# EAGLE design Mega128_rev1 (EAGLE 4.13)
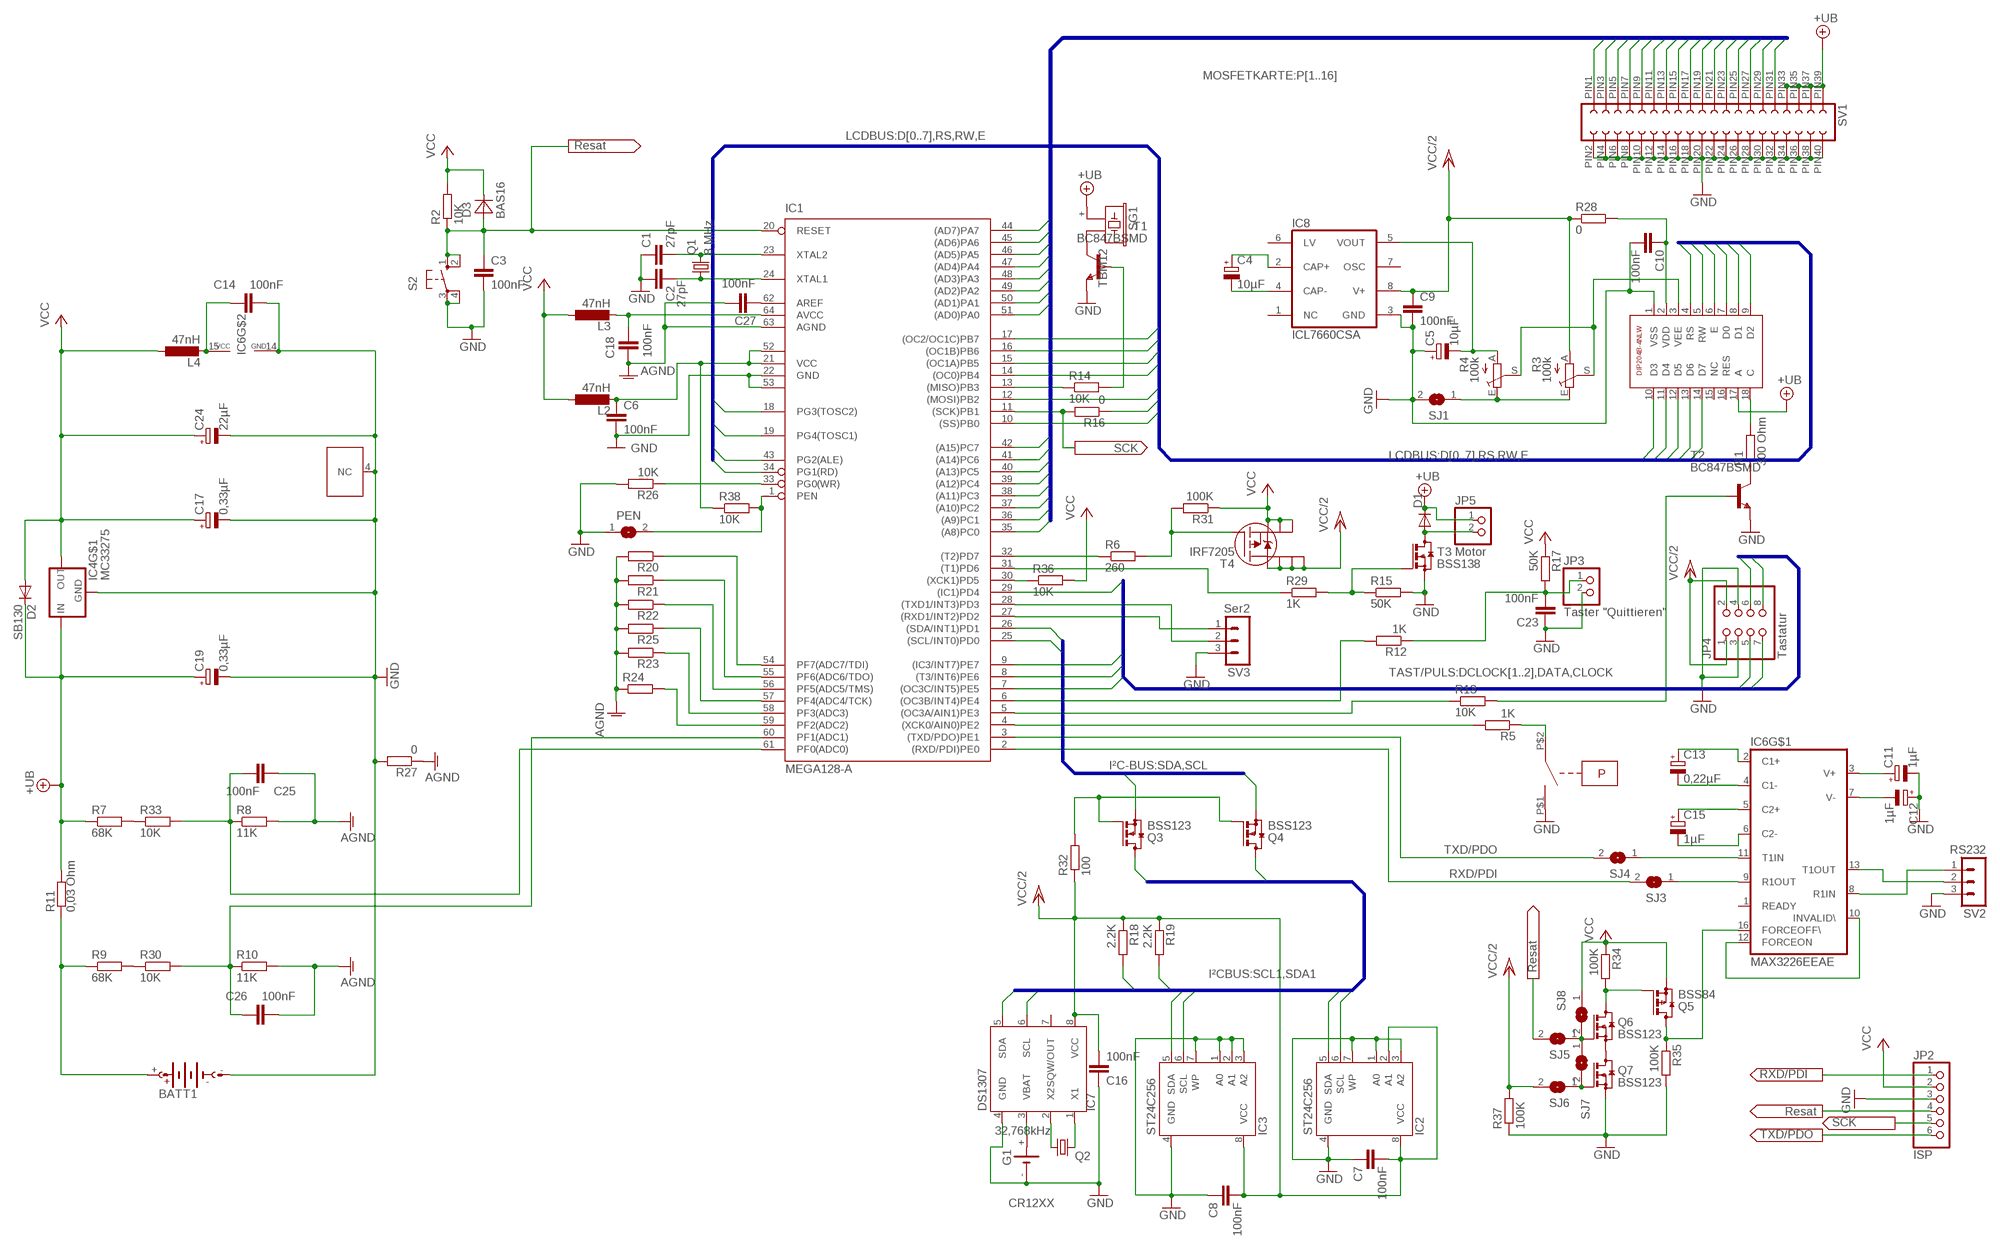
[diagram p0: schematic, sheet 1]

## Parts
BATT1  LITHIUM11.1  [AB9V]
C1  27pF  C-EUC0805K  [C0805K]
C2  27pF  C-EUC0805K  [C0805K]
C3  100nF  C-EUC0805K  [C0805K]
C4  10µF  CPOL-EUC/6032-28R  [C/6032-28R]
C5  10µF  CPOL-EUC/6032-28R  [C/6032-28R]
C6  100nF  C-EUC0805K  [C0805K]
C7  100nF  C-EUC0805K  [C0805K]
C8  100nF  C-EUC0805K  [C0805K]
C9  100nF  C-EUC0805K  [C0805K]
C10  100nF  C-EUC0805K  [C0805K]
C11  1µF  CPOL-EUA  [PANASONIC_A]
C12  1µF  CPOL-EUA  [PANASONIC_A]
C13  0,22µF  CPOL-EUA  [PANASONIC_A]
C14  100nF  C-EUC0805K  [C0805K]
C15  1µF  CPOL-EUA  [PANASONIC_A]
C16  100nF  C-EUC0805K  [C0805K]
C17  0,33µF  CPOL-EUA/3216-18R  [A/3216-18R]
C18  100nF  C-EUC0805K  [C0805K]
C19  0,33µF  CPOL-EUA/3216-18R  [A/3216-18R]
C23  100nF  C-EUC0805K  [C0805K]
C24  22µF  CPOL-EU085CS-1AR  [085CS_1AR]
C25  100nF  C-EUC0805K  [C0805K]
C26  100nF  C-EUC0805K  [C0805K]
C27  100nF  C-EUC0805K  [C0805K]
D1  DIODE-MICROMELF-W  [MICROMELF-W]
D2  SB130  DIODE-F126-10  [F126-10]
D3  BAS16  [SOT23]
G1  CR12XX  [CR12XXH]
IC1  MEGA128-A  [TQFP64]
IC2  ST24C256  AT24C  [SOIC8]
IC3  ST24C256  AT24C  [SOIC8]
IC4  MC33275  [SOT223]
IC6  MAX3226EEAE  [SSOP16]
IC7  DS1307  [SOIC-8]
IC8  ICL7660CSA  [SO08]
JP2  ISP  PINHD-1X6  [1X06]
JP3  Taster "Quittieren"  PINHD-1X2  [1X02]
JP4  Tastatur  PINHD-2X4  [2X04]
JP5  Motor  PINHD-1X2  [1X02]
L2  47nH  L-EU0805  [R0805]
L3  47nH  L-EU0805  [R0805]
L4  47nH  L-EU0805  [R0805]
PEN  SJ  [SJ]
Q1  8 MHz  CRYTALHC49U-V  [HC49U-V]
Q2  32,768kHz  CRYTALTC26H  [TC26H]
Q3  BSS123  [SOT23]
Q4  BSS123  [SOT23]
Q5  BSS84  [SOT23]
Q6  BSS123  [SOT23]
Q7  BSS123  [SOT23]
R1  300 Ohm  R-EU_M1206  [M1206]
R2  10K  R-EU_R0805W  [R0805W]
R3  100k  TRIM_EU-S75H  [S75H]
R4  100k  TRIM_EU-S75H  [S75H]
R5  1K  R-EU_R0805W  [R0805W]
R6  260  R-EU_R0805W  [R0805W]
R7  68K  R-EU_R0805W  [R0805W]
R8  11K  R-EU_R0805W  [R0805W]
R9  68K  R-EU_R0805W  [R0805W]
R10  11K  R-EU_R0805W  [R0805W]
R11  0,03 Ohm  13F  [13F]
R12  1K  R-EU_R0805W  [R0805W]
R13  10K  R-EU_R0805W  [R0805W]
R14  10K  R-EU_R0805W  [R0805W]
R15  50K  R-EU_R0805W  [R0805W]
R16  0  R-EU_R0805W  [R0805W]
R17  50K  R-EU_R0805W  [R0805W]
R18  2.2K  R-EU_R0805W  [R0805W]
R19  2.2K  R-EU_R0805W  [R0805W]
R20  R-EU_R0805W  [R0805W]
R21  R-EU_R0805W  [R0805W]
R22  R-EU_R0805W  [R0805W]
R23  R-EU_R0805W  [R0805W]
R24  R-EU_R0805W  [R0805W]
R25  R-EU_R0805W  [R0805W]
R26  10K  R-EU_R0805W  [R0805W]
R27  0  R-EU_R0805W  [R0805W]
R28  0  R-EU_R0805W  [R0805W]
R29  1K  R-EU_R0805W  [R0805W]
R30  10K  R-EU_R0805W  [R0805W]
R31  100K  R-EU_R0805W  [R0805W]
R32  100  R-EU_R0805W  [R0805W]
R33  10K  R-EU_R0805W  [R0805W]
R34  100K  R-EU_R0805W  [R0805W]
R35  100K  R-EU_R0805W  [R0805W]
R36  10K  R-EU_R0805W  [R0805W]
R37  100K  R-EU_R0805W  [R0805W]
R38  10K  R-EU_R0805W  [R0805W]
S1  Druckschalter  6761  [6761]
S2  10-XX  [B3F-10XX]
SG1  TBM12  TBM05  [F/CM12P]
SJ1  SJ  [SJ]
SJ3  SJ  [SJ]
SJ4  SJ  [SJ]
SJ5  SJ  [SJ]
SJ6  SJ  [SJ]
SJ7  SJ  [SJ]
SJ8  SJ  [SJ]
SV1  FE20-2W2MMRAST  [FE20-2W-2MM]
SV2  RS232  MA03-1  [MA03-1]
SV3  Ser2  MA03-1  [MA03-1]
T1  BC847BSMD  [SOT23]
T2  BC847BSMD  [SOT23]
T3  BSS138  [SOT23]
T4  IRF7205  [SO8-2]
U$2  DIP204B-4NLW  [DIP204B-4NLW]

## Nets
+UB [pwr]: C19.+ D1.C D2.C IC4.1(IN) JP5.1 R7.1 R11.P$1 SG1.+ SV1.PIN33 SV1.PIN35 SV1.PIN37 SV1.PIN39 U$2.17(A)
AGND: C18.1 C25.2 C26.1 C27.2 IC1.63(AGND) R8.2 R10.2 R20.2 R21.2 R22.2 R23.2 R24.1 R25.2 R27.1
B+: BATT1.+ R9.1 R11.P$2
CLOCK: IC1.7((OC3C/INT5)PE5) JP4.8
D0: IC1.34(PG1(RD)) U$2.7(D0)
D1: IC1.43(PG2(ALE)) U$2.8(D1)
D2: IC1.19(PG4(TOSC1)) U$2.9(D2)
D3: IC1.18(PG3(TOSC2)) U$2.10(D3)
D4: IC1.14((OC0)PB4) U$2.11(D4)
D5: IC1.15((OC1A)PB5) U$2.12(D5)
D6: IC1.16((OC1B)PB6) U$2.13(D6)
D7: IC1.17((OC2/OC1C)PB7) U$2.14(D7)
DATA: IC1.29((IC1)PD4) JP4.6
DCLOCK1: IC1.9((IC3/INT7)PE7) JP4.5
DCLOCK2: IC1.8((T3/INT6)PE6) JP4.7
E: IC1.12((MOSI)PB2) U$2.6(E)
GND: BATT1.- C1.1 C2.2 C3.2 C5.+ C6.2 C7.1 C8.1 C9.2 C10.2 C11.- C12.+ C14.1 C16.1 C17.- C19.- C23.1 C24.- G1.- IC1.22(GND) IC1.53(GND1) IC2.1(A0) IC2.3(A2) IC2.4(GND) IC2.7(WP) IC3.1(A0) IC3.2(A1) IC3.3(A2) IC3.4(GND) IC3.7(WP) IC4.2(GND) IC4.4(NC) IC6.14(GND) IC7.4(GND) IC8.3(GND) JP2.3 JP3.2 JP4.3 JP4.4 PEN.1 Q7.2(S) R15.2 R26.2 R27.2 R35.2 R37.1 S1.P$1 S2.3(P) S2.4(P1) SJ1.2 SV1.PIN2 SV1.PIN4 SV1.PIN6 SV1.PIN8 SV1.PIN10 SV1.PIN12 SV1.PIN14 SV1.PIN16 SV1.PIN18 SV1.PIN20 SV1.PIN22 SV1.PIN24 SV1.PIN26 SV1.PIN28 SV1.PIN30 SV1.PIN32 SV1.PIN34 SV1.PIN36 SV1.PIN38 SV1.PIN40 SV2.3 SV3.3 T1.2(E) T2.2(E) T3.2(S) U$2.1(VSS)
IBATT: C25.1 IC1.61(PF0(ADC0)) R8.1 R33.2
N$1: IC7.2(X2) Q2.1
N$2: IC7.1(X1) Q2.2
N$3: C4.+ IC8.2(CAP+)
N$4: C5.- IC8.5(VOUT) R4.A
N$5: C4.- IC8.4(CAP-)
N$6 [pwr]: R1.2 U$2.18(C)
N$7: R3.S R4.S U$2.3(VEE)
N$8: IC1.4((XCK0/AIN0)PE2) R5.2
N$9: C27.1 IC1.62(AREF)
N$10: IC6.13(T1OUT) SV2.2
N$11: R13.2 T2.1(B)
N$12: R5.1 S1.P$2
N$13: R3.E R4.E SJ1.1
N$14: IC1.5((OC3A/AIN1)PE3) R13.1
N$15: IC1.13((MISO)PB3) R14.1
N$16: C10.1 R28.2 U$2.2(VDD)
N$17: C11.+ IC6.3(V+)
N$18: C12.- IC6.7(V-)
N$19: Q3.1(G) Q4.1(G) R32.2
N$20: IC1.54(PF7(ADC7/TDI)) R20.1
N$21: R9.2 R30.1
N$22: C15.- IC6.6(C2-)
N$23: C15.+ IC6.5(C2+)
N$24: C13.- IC6.4(C1-)
N$25: C13.+ IC6.2(C1+)
N$26: IC6.8(R1IN) SV2.1
N$27: IC1.32((T2)PD7) R6.1
N$28: IC1.6((OC3B/INT4)PE4) R12.2
N$29: C23.2 JP3.1 R12.1 R17.2
N$30: R1.1 T2.3(C)
N$31: IC1.55(PF6(ADC6/TDO)) R21.1
N$32: IC1.1(PEN) PEN.2 R38.2
N$33: C1.2 IC1.23(XTAL2) Q1.2
N$34: C2.1 IC1.24(XTAL1) Q1.1
N$35: R15.1 R29.2 T3.1(G)
N$36: SG1.- T1.3(C)
N$37: R14.2 T1.1(B)
N$38: R6.2 R31.2 T4.4(G)
N$39: G1.+ IC7.3(VBAT)
N$40: IC1.33(PG0(WR)) R26.1
N$41: C6.1 IC1.21(VCC) IC1.52(VCC1) L2.2 R38.1
N$42: IC1.56(PF5(ADC5/TMS)) R22.1
N$43: C18.2 IC1.64(AVCC) L3.2
N$44: IC1.58(PF3(ADC3)) R23.1
N$45 [pwr]: D1.A JP5.2 T3.3(D)
N$46: IC1.59(PF2(ADC2)) R24.2
N$48: IC6.11(T1IN) SJ4.1
N$49: IC6.9(R1OUT) SJ3.1
N$50: R7.2 R33.1
N$51: IC1.31((T1)PD6) R29.1
N$52: C14.2 IC6.15(VCC) L4.2
N$53: IC1.28((TXD1/INT3)PD3) SV3.2
N$54: IC1.27((RXD1/INT2)PD2) SV3.1
N$55: Q6.2(S) Q7.3(D)
N$56: Q5.1(G) Q6.3(D) R34.2
N$57: Q6.1(G) SJ5.1 SJ7.1 SJ8.2
N$58: IC6.16(FORCEOFF\) Q5.3(D) R35.1
N$59: Q7.1(G) SJ6.1 SJ7.2
N$60: IC1.30((XCK1)PD5) R36.1
N$61: IC1.57(PF4(ADC4/TCK)) R25.1
P1: IC1.51((AD0)PA0) SV1.PIN31
P2: IC1.50((AD1)PA1) SV1.PIN29
P3: IC1.49((AD2)PA2) SV1.PIN27
P4: IC1.48((AD3)PA3) SV1.PIN25
P5: IC1.47((AD4)PA4) SV1.PIN23
P6: IC1.46((AD5)PA5) SV1.PIN21
P7: IC1.45((AD6)PA6) SV1.PIN19
P8: IC1.44((AD7)PA7) SV1.PIN17
P9: IC1.35((A8)PC0) SV1.PIN1
P10: IC1.36((A9)PC1) SV1.PIN3
P11: IC1.37((A10)PC2) SV1.PIN5
P12: IC1.38((A11)PC3) SV1.PIN7
P13: IC1.39((A12)PC4) SV1.PIN9
P14: IC1.40((A13)PC5) SV1.PIN11
P15: IC1.41((A14)PC6) SV1.PIN13
P16: IC1.42((A15)PC7) SV1.PIN15
RESAT: C3.1 D3.1(A) IC1.20(RESET) JP2.4 R2.1 S2.1(S) S2.2(S1) SJ5.2
RS: IC1.10((SS)PB0) U$2.4(RS)
RW: R16.1 U$2.5(RW)
RXD/PDI: IC1.2((RXD/PDI)PE0) IC6.10(INVALID\) IC6.12(FORCEON) JP2.1 SJ3.2
SCK: IC1.11((SCK)PB1) JP2.5 R16.2
SCL: IC1.25((SCL/INT0)PD0) Q4.2(S) R19.2
SCL1 [pwr]: IC2.6(SCL) IC3.6(SCL) IC7.6(SCL) Q4.3(D)
SDA: IC1.26((SDA/INT1)PD1) Q3.2(S) R18.2
SDA1 [pwr]: IC2.5(SDA) IC3.5(SDA) IC7.5(SDA) Q3.3(D)
TXD/PDO: IC1.3((TXD/PDO)PE1) JP2.6 SJ4.2
VBATT: C26.2 IC1.60(PF1(ADC1)) R10.1 R30.2
VCC: C17.+ C24.+ D2.A D3.3(C) IC4.3(OUT) JP2.2 L2.1 L3.1 L4.1 Q5.2(S) R2.2 R17.1 R31.1 R34.1 R36.2 SJ8.1 T4.1(S) T4.2(S1) T4.3(S2)
VCC/2: C7.2 C8.2 C9.1 C16.2 IC2.2(A1) IC2.8(VCC) IC3.8(VCC) IC7.8(VCC) IC8.8(V+) JP4.1 JP4.2 R3.A R18.1 R19.1 R28.1 R32.1 R37.2 SJ6.2 T4.5(D) T4.6(D) T4.7(D) T4.8(D)
Unconnected: IC6.1(READY) IC7.7(SQW/OUT) IC8.1(NC) IC8.6(LV) IC8.7(OSC) U$2.15(NC) U$2.16(RES)

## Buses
MOSFETKARTE:P[1..16]
LCDBUS:D[0..7],RS,RW,E
TAST/PULS:DCLOCK[1..2],DATA,CLOCK
I²CBUS:SCL1,SDA1
I²C-BUS:SDA,SCL

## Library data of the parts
BATT1 = battery:LITHIUM11.1
C1-C3 C6-C10 C14 C16 C18 C23 C25-C27 = rcl:C-EU: CAPACITOR, European symbol
C4 C5 C11-C13 C15 C17 C19 C24 = rcl:CPOL-EU: POLARIZED CAPACITOR, European symbol
D1 D2 = diode:DIODE-: DIODE
D3 = diode:BAS16: BAS16
G1 = battery:CR12XX
IC1 = avr:MEGA128: MICROCONTROLLER 128 Kbytes FLASH 4 Kbytes SRAM 4 Kbytes EEPROM DUAL USART 8-channel 10 bit ADC
IC2 IC3 = atmel:AT24C*: 2-wire serial EEPROM
IC4 = v-reg:MC33275: LDO Spannungsregler von ON Semiconductor * niedriger Stromverbrauch im Leerlauf * Vin max: 13V * Vout: 5V * Iout: 300mA
IC6 = maxim:MAX3226EEAE
IC7 = dallas:DS1307: I2C Serial RTC w/56 bytes battery backed RAM
IC8 = maxim:ICL7660CSA: VOLTAGE CONVERTER
JP2 = pinhead:PINHD-1X6: PIN HEADER
JP3 JP5 = pinhead:PINHD-1X2: PIN HEADER
JP4 = pinhead:PINHD-2X4: PIN HEADER
L2-L4 = rcl:L-EU: INDUCTOR, European symbol
PEN SJ1 SJ3-SJ8 = jumper:SJ: SMD solder JUMPER
Q1 Q2 = crystal:CRYTAL: CRYSTAL
Q3 Q4 Q6 Q7 = transistor-small-signal:BSS123: N-CHANNEL MOS FET
Q5 = transistor-small-signal:BSS84: P-CHANNEL MOS FET
R1 R2 R5-R10 R12-R38 = rcl:R-EU_: RESISTOR, European symbol
R3 R4 = pot:TRIM_EU-: POTENTIOMETER
R11 = resistor-shunt:13F
S1 = herga:6761
S2 = switch-omron:10-XX: OMRON SWITCH
SG1 = buzzer:TBM05: BUZZER
SV1 = con-lsta:FE20-2W: FEMALE HEADER
SV2 SV3 = con-lstb:MA03-1: PIN HEADER
T1 T2 = transistor-npn:BC847*: NPN Transistor
T3 = transistor-small-signal:BSS138
T4 = irf-2:IRF7205: IRF7205 P-Channel Hexfet von International Rectifier VDSS = -30V RDS(on) = 0.070 Ohm @ -10V ID = -4.6A
U$2 = dip204b-4nlw:DIP204B-4NLW

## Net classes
1 pwr: width 0.61 mm, clearance 0.61 mm

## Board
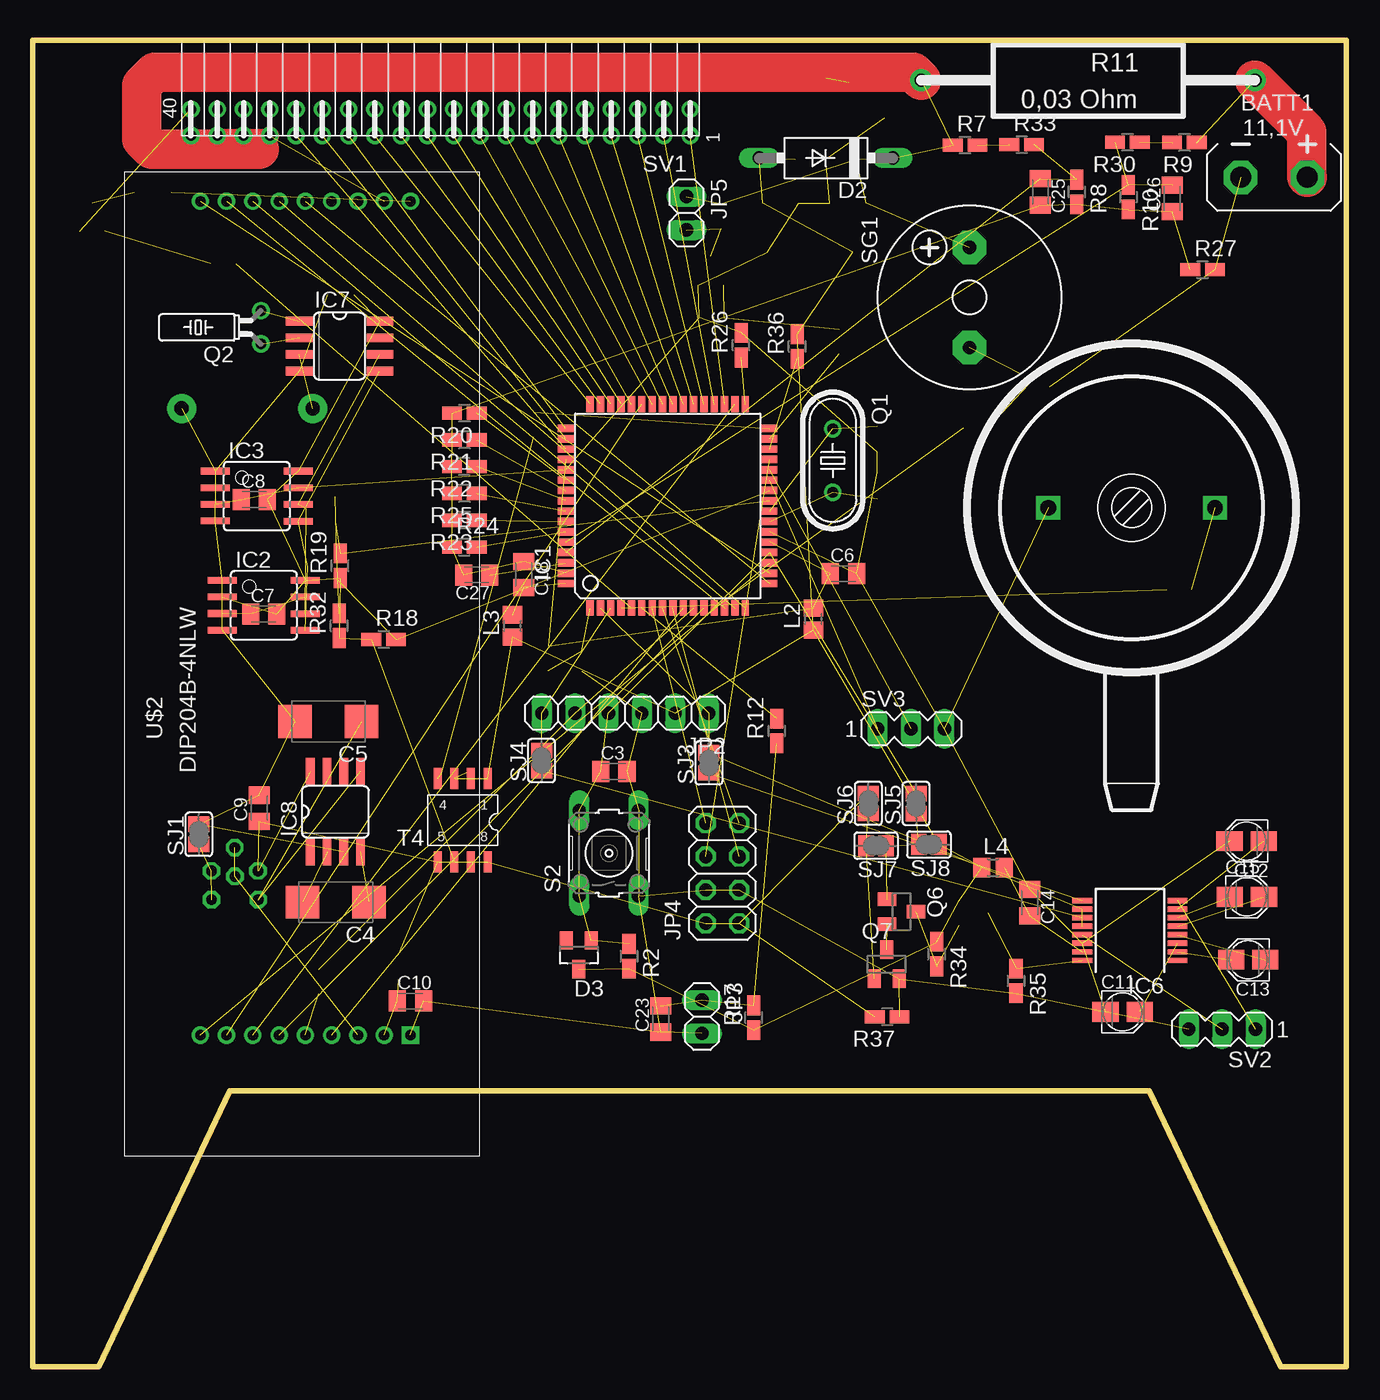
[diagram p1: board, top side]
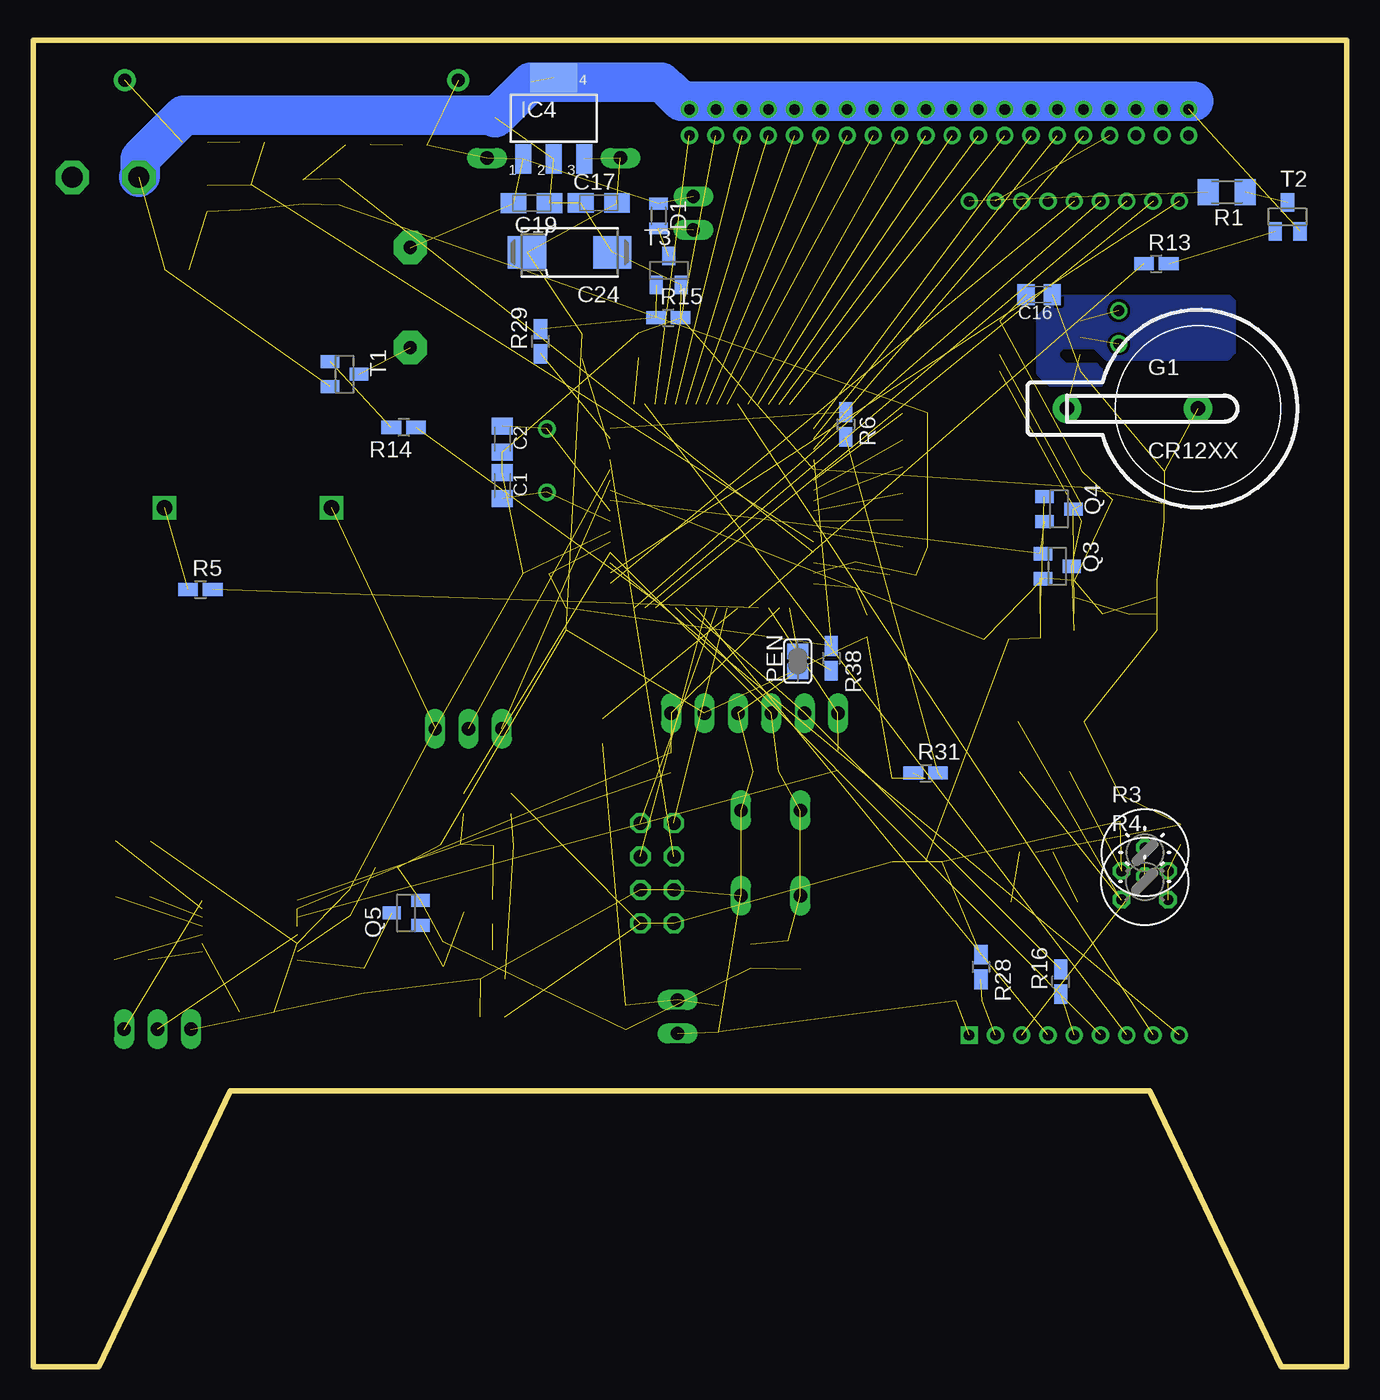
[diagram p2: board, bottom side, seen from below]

Size 100 x 101 mm. Coordinates in mm from the lower left corner, seen from the top.
Outline: 0,101 100,101 100,0 95,0 85,21 15,21 5,0 0,0 0,101
Copper layers (1*16): Top 0.035mm / dielectric 1.5mm / Bottom 0.035mm
Design rules "default": minimum track width 10mil, minimum drill 24mil, track to track 8mil, track to pad 8mil, pad to pad 8mil, via to via 8mil, smd to smd 8mil, copper to edge 0.5mm, drill to drill 8mil, minimum pad ring 10mil, minimum via ring 8mil, stop-mask expansion 4mil, vias tented up to drill 0mil, thermal gap 10mil

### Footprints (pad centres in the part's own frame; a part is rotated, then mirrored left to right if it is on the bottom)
AB9V = drill 1.6 pad 2.54 octagon: + 0,2.54; - 0,-2.54
C0805K = smd 1.3 x 1.6: 1 -1,0; 2 1,0
C/6032-28R = smd 2.55 x 2.5: + 2.525,0; - -2.525,0
PANASONIC_A = smd 2 x 1.5: + 1.3,0; - -1.3,0
A/3216-18R = smd 1.95 x 1.5: + 1.375,0; - -1.375,0
085CS_1AR = smd 2.9 x 2.5: + 3.25,0; - -3.25,0
MICROMELF-W = smd 0.9 x 1.4: A 0.95,0; C -0.95,0
F126-10 = drill 1.016 long: A 5.08,0; C -5.08,0
SOT23 = smd 1 x 1.4: 1 -0.95,-1.1; 2 0.95,-1.1; 3 0,1.1
CR12XXH = drill 1.1 pad 2.184 round: + -9.98,0; - 0,0
TQFP64 = smd 1.194 x 0.559: 1 -7.76,5.905; 2 -7.76,5.118; 3 -7.76,4.331; 4 -7.76,3.543; 5 -7.76,2.756; 6 -7.76,1.968; 7 -7.76,1.181; 8 -7.76,0.394; 9 -7.76,-0.394; 10 -7.76,-1.181; 11 -7.76,-1.968; 12 -7.76,-2.756; 13 -7.76,-3.543; 14 -7.76,-4.331; 15 -7.76,-5.118; 16 -7.76,-5.905; 33 7.76,-5.905; 34 7.76,-5.118; 35 7.76,-4.331; 36 7.76,-3.543; 37 7.76,-2.756; 38 7.76,-1.968; 39 7.76,-1.181; 40 7.76,-0.394; 41 7.76,0.394; 42 7.76,1.181; 43 7.76,1.968; 44 7.76,2.756; 45 7.76,3.543; 46 7.76,4.331; 47 7.76,5.118; 48 7.76,5.905 | smd 0.559 x 1.194: 17 -5.905,-7.76; 18 -5.118,-7.76; 19 -4.331,-7.76; 20 -3.543,-7.76; 21 -2.756,-7.76; 22 -1.968,-7.76; 23 -1.181,-7.76; 24 -0.394,-7.76; 25 0.394,-7.76; 26 1.181,-7.76; 27 1.968,-7.76; 28 2.756,-7.76; 29 3.543,-7.76; 30 4.331,-7.76; 31 5.118,-7.76; 32 5.905,-7.76; 49 5.905,7.76; 50 5.118,7.76; 51 4.331,7.76; 52 3.543,7.76; 53 2.756,7.76; 54 1.968,7.76; 55 1.181,7.76; 56 0.394,7.76; 57 -0.394,7.76; 58 -1.181,7.76; 59 -1.968,7.76; 60 -2.756,7.76; 61 -3.543,7.76; 62 -4.331,7.76; 63 -5.118,7.76; 64 -5.905,7.76
SOIC8 = smd 0.5 x 2.2: 1 -1.905,-3.154; 2 -0.645,-3.154; 3 0.625,-3.154; 4 1.895,-3.154; 5 1.905,3.154; 6 0.635,3.154; 7 -0.635,3.154; 8 -1.905,3.154
SOT223 = smd 1.219 x 2.235: 1 -2.311,-3.099; 2 0,-3.099; 3 2.311,-3.099 | smd 3.6 x 2.2: 4 0,3.099
SSOP16 = smd 0.4 x 1.5: 1 -2.275,-3.625; 2 -1.625,-3.625; 3 -0.975,-3.625; 4 -0.325,-3.625; 5 0.325,-3.625; 6 0.975,-3.625; 7 1.625,-3.625; 8 2.275,-3.625; 9 2.275,3.625; 10 1.625,3.625; 11 0.975,3.625; 12 0.325,3.625; 13 -0.325,3.625; 14 -0.975,3.625; 15 -1.625,3.625; 16 -2.275,3.625
SOIC-8 = smd 2.032 x 0.66: 1 -3.073,1.27; 2 -3.073,0; 3 -3.073,-1.27; 4 -3.073,-2.54; 5 3.073,-2.54; 6 3.073,-1.27; 7 3.073,0; 8 3.073,1.27
SO08 = smd 0.66 x 2.032: 1 -1.905,-3.073; 2 -0.635,-3.073; 3 0.635,-3.073; 4 1.905,-3.073; 5 1.905,3.073; 6 0.635,3.073; 7 -0.635,3.073; 8 -1.905,3.073
1X06 = drill 1.016 long: 1 -6.35,0; 2 -3.81,0; 3 -1.27,0; 4 1.27,0; 5 3.81,0; 6 6.35,0
1X02 = drill 1.016 long: 1 -1.27,0; 2 1.27,0
2X04 = drill 1.016 octagon: 1 -3.81,-1.27; 2 -3.81,1.27; 3 -1.27,-1.27; 4 -1.27,1.27; 5 1.27,-1.27; 6 1.27,1.27; 7 3.81,-1.27; 8 3.81,1.27
R0805 = smd 1.3 x 1.5: 1 -0.85,0; 2 0.85,0
SJ = smd 1.168 x 1.6: 1 -0.762,0; 2 0.762,0
HC49U-V = drill 0.813 round: 1 -2.413,0; 2 2.413,0
TC26H = drill 0.813 round: 1 -1.27,0; 2 1.27,0
M1206 = smd 1.6 x 2: 1 -1.4,0; 2 1.4,0
R0805W = smd 1.5 x 1: 1 -0.94,0; 2 0.94,0
S75H = drill 0.813 octagon: A -1.778,-1.397; E 1.778,-1.397; S 0,0.381
13F = drill 1 pad 1.676 round: P$1 12.7,0; P$2 -12.7,0
6761 = drill 1.2 square: P$1 -6.35,0; P$2 6.35,0
B3F-10XX = drill 1.016 long: 1 -3.251,2.261; 2 3.251,2.261; 3 -3.251,-2.261; 4 3.251,-2.261
F/CM12P = drill 1.016 pad 2.54 octagon: + 3.81,0; - -3.81,0
FE20-2W-2MM = drill 0.8 round: PIN1 -19,1; PIN2 -19,-1; PIN3 -17,1; PIN4 -17,-1; PIN5 -15,1; PIN6 -15,-1; PIN7 -13,1; PIN8 -13,-1; PIN9 -11,1; PIN10 -11,-1; PIN11 -9,1; PIN12 -9,-1; PIN13 -7,1; PIN14 -7,-1; PIN15 -5,1; PIN16 -5,-1; PIN17 -3,1; PIN18 -3,-1; PIN19 -1,1; PIN20 -1,-1; PIN21 1,1; PIN22 1,-1; PIN23 3,1; PIN24 3,-1; PIN25 5,1; PIN26 5,-1; PIN27 7,1; PIN28 7,-1; PIN29 9,1; PIN30 9,-1; PIN31 11,1; PIN32 11,-1; PIN33 13,1; PIN34 13,-1; PIN35 15,1; PIN36 15,-1; PIN37 17,1; PIN38 17,-1; PIN39 19,1; PIN40 19,-1
MA03-1 = drill 1.016 long: 1 -2.54,0; 2 0,0; 3 2.54,0
SO8-2 = smd 0.61 x 1.626: 1 -2.54,-2.54; 2 -1.27,-2.54; 3 0,-2.54; 4 1.27,-2.54; 5 1.27,3.81; 6 0,3.81; 7 -1.27,3.81; 8 -2.54,3.81
DIP204B-4NLW = drill 0.8 square: 1 9.25,5.25 | drill 0.8 round: 2 9.25,7.25; 3 9.25,9.25; 4 9.25,11.25; 5 9.25,13.25; 6 9.25,15.25; 7 9.25,17.25; 8 9.25,19.25; 9 9.25,21.25; 10 72.75,21.25; 11 72.75,19.25; 12 72.75,17.25; 13 72.75,15.25; 14 72.75,13.25; 15 72.75,11.25; 16 72.75,9.25; 17 72.75,7.25; 18 72.75,5.25

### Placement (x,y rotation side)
BATT1  94.49,90.57 270 top
C1  64.28,67.1 270 bottom
C2  64.28,70.64 270 bottom
C3  44.23,45.33 0 top
C4  23.06,35.38 180 top
C5  22.5,49.13 180 top
C6  61.71,60.39 0 top
C7  17.58,57.31 0 top
C8  16.85,66.03 0 top
C9  17.23,42.52 90 top
C10  28.75,27.84 0 top
C11  82.97,27.02 0 top
C12  92.41,40.02 180 top
C13  92.53,30.99 180 top
C14  75.9,35.33 270 top
C15  92.42,35.78 0 top
C16  23.42,81.64 180 bottom
C17  56.94,88.62 0 bottom
C18  37.37,60.33 270 top
C19  62.06,88.61 180 bottom
C23  47.8,26.48 90 top
C24  59.16,84.86 180 bottom
C25  76.71,89.47 270 top
C26  86.75,88.97 90 top
C27  33.79,60.3 180 top
D1  52.4,87.63 270 bottom
D2  60.38,92.04 180 top
D3  41.57,31.36 180 top
G1  11.33,72.96 0 bottom
IC1  48.33,65.55 90 top
IC2  17.58,57.98 270 top
IC3  17.04,66.3 270 top
IC4  60.37,95.07 0 bottom
IC6  83.52,33.22 90 top
IC7  23.35,78.36 0 top
IC8  23.03,42.26 0 top
JP2  45.09,49.77 180 top
JP3  50.94,26.65 270 top
JP4  52.5,37.58 90 top
JP5  49.75,87.84 270 top
L2  59.42,56.94 90 top
L3  36.52,56.41 90 top
L4  73.1,38.01 0 top
PEN  41.8,53.73 90 bottom
Q1  60.9,69.01 270 top
Q2  17.36,79.15 90 top
Q3  22.04,60.95 270 bottom
Q4  21.92,65.32 270 bottom
Q5  71.61,34.56 90 bottom
Q6  66.13,34.65 270 top
Q7  65,30.65 0 top
R1  9.13,89.45 180 bottom
R2  45.39,31.26 270 top
R3  15.37,39.15 0 bottom
R4  15.38,36.96 0 bottom
R5  87.27,59.18 0 bottom
R6  38.15,71.75 270 bottom
R7  70.97,93.03 0 top
R8  79.46,89.46 270 top
R9  87.67,93.23 180 top
R10  83.4,89.06 270 top
R11  80.34,97.96 180 top
R12  56.64,48.41 90 top
R13  14.5,83.99 0 bottom
R14  71.8,71.53 180 bottom
R15  51.66,79.88 0 bottom
R16  21.77,29.32 90 bottom
R17  54.88,26.58 90 top
R18  26.71,55.39 0 top
R19  23.39,61 90 top
R20  32.86,72.61 180 top
R21  32.86,70.58 180 top
R22  32.85,68.55 180 top
R23  32.86,64.46 180 top
R24  32.85,62.42 0 top
R25  32.86,66.51 180 top
R26  53.92,77.79 90 top
R27  89.05,83.54 0 top
R28  27.85,30.44 270 bottom
R29  61.38,78.08 90 bottom
R30  83.33,93.24 180 top
R31  32.06,45.2 0 bottom
R32  23.33,56.43 90 top
R33  75.28,93.07 0 top
R34  68.8,31.42 270 top
R35  74.85,29.38 270 top
R36  58.2,77.7 90 top
R37  65.04,26.64 180 top
R38  39.24,53.94 270 bottom
S1  83.65,65.41 0 top
S2  43.86,39.11 90 top
SG1  71.3,81.42 90 top
SJ1  12.64,40.54 90 top
SJ3  51.47,45.98 90 top
SJ4  38.73,46.16 90 top
SJ5  67.24,42.88 90 top
SJ6  63.61,42.89 90 top
SJ7  64.19,39.67 180 top
SJ8  68.21,39.76 180 top
SV1  31.04,94.76 180 top
SV2  90.54,25.7 180 top
SV3  66.86,48.59 0 top
T1  76.3,75.58 270 bottom
T2  4.51,87.56 0 bottom
T3  51.61,83.48 0 bottom
T4  32.08,42.25 180 top
U$2  34,16 90 top

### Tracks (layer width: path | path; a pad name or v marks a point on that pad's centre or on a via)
+UB  (8 unrouted)
  Top 1.016: 13.95,93.67 13.01,92.73 12.02,92.73 12.02,93.74 SV1.PIN39 | 13.95,93.67 14.01,93.73 | 17.25,92.7 13.95,93.67 | SV1.PIN33 SV1.PIN35 16.01,93.73 14.01,93.73 | 14.01,93.73 SV1.PIN37
  Top 1.422: SV1.PIN33
  Top 3: R11.P$1 67.02,98.58 9.28,98.58 8.28,97.58 8.28,93.47 9.04,92.71 17.25,92.7
AGND  (13 unrouted)
B+  (1 unrouted)
  Top 3: BATT1.+ 96.97,90.63 96.97,94.03 R11.P$2
CLOCK  (1 unrouted)
D0  (1 unrouted)
D1  (1 unrouted)
D2  (1 unrouted)
D3  (1 unrouted)
D4  (1 unrouted)
D5  (1 unrouted)
D6  (1 unrouted)
D7  (1 unrouted)
DATA  (1 unrouted)
DCLOCK1  (1 unrouted)
DCLOCK2  (1 unrouted)
E  (1 unrouted)
GND  (55 unrouted)
  Bottom 1.016: SV1.PIN40 SV1.PIN38 | 18.06,95.78 18.18,95.78 18.19,95.77 SV1.PIN32 | 18.06,95.78 SV1.PIN34 | 18.06,95.78 16.06,95.78 SV1.PIN36 15.55,96.25 11.67,96.25 11.67,96.13 SV1.PIN40 | SV1.PIN40 11.7,96.1 11.7,96.31 11.64,96.37 | SV1.PIN30 SV1.PIN32 | SV1.PIN32 | SV1.PIN28 SV1.PIN26 26.06,95.78 28.02,95.78 SV1.PIN24 28.06,95.78 30.02,95.78 SV1.PIN22 SV1.PIN20 SV1.PIN18 34.06,95.74 36.06,95.74 | 36.06,95.74 36.09,95.74 | 36.06,95.74 SV1.PIN16 | 36.06,95.74 38.02,95.74 SV1.PIN14 SV1.PIN12 SV1.PIN10 SV1.PIN8 | SV1.PIN8 | SV1.PIN8 SV1.PIN6 46.06,95.74 48.02,95.74 SV1.PIN4 48.06,95.74 50.02,95.74 SV1.PIN2 50.05,95.78 50.06,95.78 50.65,96.37
  Bottom 3: 11.65,96.38 11.64,96.37 50.65,96.37 51.53,97.25 52.18,97.83 62.12,97.83 64.84,95.11 65.04,95.31 88.54,95.31 91.85,92 91.85,90.67 BATT1.-
  pour Bottom: 21.95,77.32 21.62,77.65 19.19,77.65 18.31,76.77 9.08,76.77 8.55,77.3 8.56,81.1 8.9,81.44 21.99,81.44 22.45,80.99 23.51,79.93 23.51,75.67 22.63,74.79 18.69,74.79 18.69,75.9 19.07,76.28 21.38,76.28 21.95,76.85
IBATT  (3 unrouted)
N$1  (1 unrouted)
N$2  (1 unrouted)
N$3  (1 unrouted)
N$4  (2 unrouted)
N$5  (1 unrouted)
N$6  (1 unrouted)
N$7  (2 unrouted)
N$8  (1 unrouted)
N$9  (1 unrouted)
N$10  (1 unrouted)
N$11  (1 unrouted)
N$12  (1 unrouted)
N$13  (2 unrouted)
N$14  (1 unrouted)
N$15  (1 unrouted)
N$16  (2 unrouted)
N$17  (1 unrouted)
N$18  (1 unrouted)
N$19  (2 unrouted)
N$20  (1 unrouted)
N$21  (1 unrouted)
N$22  (1 unrouted)
N$23  (1 unrouted)
N$24  (1 unrouted)
N$25  (1 unrouted)
N$26  (1 unrouted)
N$27  (1 unrouted)
N$28  (1 unrouted)
N$29  (3 unrouted)
N$30  (1 unrouted)
N$31  (1 unrouted)
N$32  (2 unrouted)
N$33  (2 unrouted)
N$34  (2 unrouted)
N$35  (2 unrouted)
N$36  (1 unrouted)
N$37  (1 unrouted)
N$38  (2 unrouted)
N$39  (1 unrouted)
N$40  (1 unrouted)
N$41  (4 unrouted)
N$42  (1 unrouted)
N$43  (2 unrouted)
N$44  (1 unrouted)
N$45  (2 unrouted)
N$46  (1 unrouted)
N$48  (1 unrouted)
N$49  (1 unrouted)
N$50  (1 unrouted)
N$51  (1 unrouted)
N$52  (2 unrouted)
N$53  (1 unrouted)
N$54  (1 unrouted)
N$55  (1 unrouted)
N$56  (2 unrouted)
N$57  (3 unrouted)
N$58  (2 unrouted)
N$59  (2 unrouted)
N$60  (1 unrouted)
N$61  (1 unrouted)
P1  (1 unrouted)
P2  (1 unrouted)
P3  (1 unrouted)
P4  (1 unrouted)
P5  (1 unrouted)
P6  (1 unrouted)
P7  (1 unrouted)
P8  (1 unrouted)
P9  (1 unrouted)
P10  (1 unrouted)
P11  (1 unrouted)
P12  (1 unrouted)
P13  (1 unrouted)
P14  (1 unrouted)
P15  (1 unrouted)
P16  (1 unrouted)
RESAT  (7 unrouted)
RS  (1 unrouted)
RW  (1 unrouted)
RXD/PDI  (4 unrouted)
SCK  (2 unrouted)
SCL  (2 unrouted)
SCL1  (3 unrouted)
SDA  (2 unrouted)
SDA1  (3 unrouted)
TXD/PDO  (2 unrouted)
VBATT  (3 unrouted)
VCC  (18 unrouted)
VCC/2  (21 unrouted)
